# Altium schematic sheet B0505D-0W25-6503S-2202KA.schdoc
size 277 x 190 mm; Device: default297x210; Symbol: default297x210; Name: default297x210; Date: 2026.02.11; Rev: V1.2; Size: "A4"; Id: /; File: B0505D-0W25-6503S-2202KA; Sheet: /
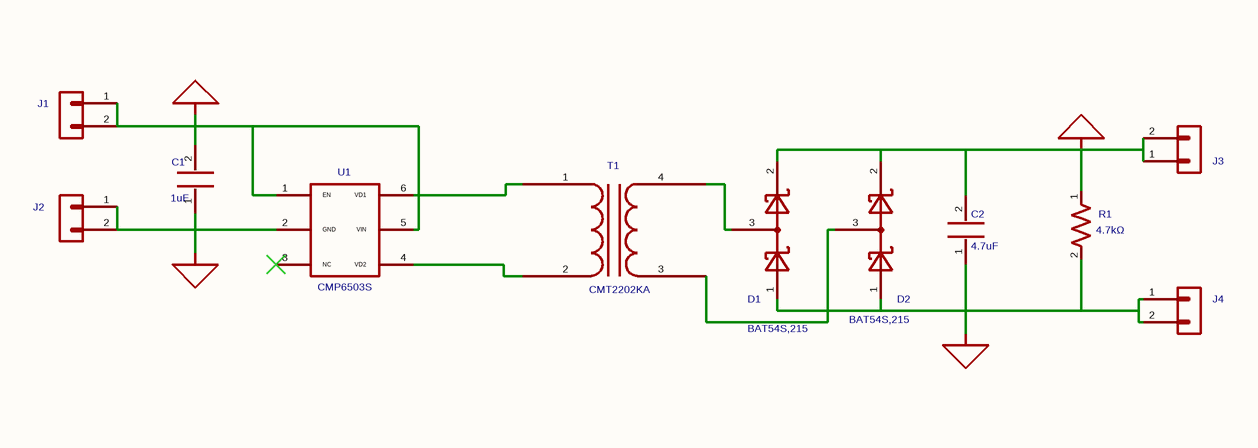
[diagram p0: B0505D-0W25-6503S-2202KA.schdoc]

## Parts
C1  1uF  [MYLibrary:C0603]
C2  4.7uF  [MYLibrary:C0603]
D1  BAT54S,215  [Package_TO_SOT_SMD:SOT-23]
D2  BAT54S,215  [Package_TO_SOT_SMD:SOT-23]
J1  KH-2.54PH180-1X2P-L11.5  [Connector_PinHeader_2.54mm:PinHeader_1x02_P2.54mm_Vertical]  (value not drawn)
J2  KH-2.54PH180-1X2P-L11.5  [Connector_PinHeader_2.54mm:PinHeader_1x02_P2.54mm_Vertical]  (value not drawn)
J3  KH-2.54PH180-1X2P-L11.5  [Connector_PinHeader_2.54mm:PinHeader_1x02_P2.54mm_Vertical]  (value not drawn)
J4  KH-2.54PH180-1X2P-L11.5  [Connector_PinHeader_2.54mm:PinHeader_1x02_P2.54mm_Vertical]  (value not drawn)
R1  4.7kΩ  [MYLibrary:R0603]
T1  CMT2202KA  [MYLibrary:CMT2202KA]
U1  CMP6503S  [MYLibrary:SOT-23-6]

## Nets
GND1: C1.1 J2.1(Pin_1) J2.2(Pin_2) U1.2(GND)
GND2: C2.1 D1.1 D2.1 J4.1(Pin_1) J4.2(Pin_2) R1.2
VCC1: C1.2 J1.1(Pin_1) J1.2(Pin_2) U1.1(EN) U1.5(VIN)
VCC2: C2.2 D1.2 D2.2 J3.1(Pin_1) J3.2(Pin_2) R1.1
NetD1_3: D1.3 T1.4(SB)
NetD2_3: D2.3 T1.3(SA)
NetT1_1: T1.1(AA) U1.6(VD1)
NetT1_2: T1.2(AB) U1.4(VD2)

Not connected (* = marked no-connect by the designer): U1 3(NC)*

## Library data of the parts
C1 = 0603B105K250NT: 容值:1uF;精度:±10%;额定电压:25V;温度系数:X7R;; Manufacturer: FH(风华); Symbol: My_Library_C; Add into BOM: yes; 3D Model: ac125912035d415993ca9572d50418b1; 3D Model Transform: 62.992,31.496,0,0,0,0,0,0,0; Tolerance: ±10%; Voltage Rating: 25V; Temperature Coefficient: X7R; ki_keywords: cap capacitor; ki_fp_filters: C_*; ModelName: C0603_L1.6-W0.8-H0.8
C2 = CL10A475KP8NNNC: 容值:4.7uF;精度:±10%;额定电压:10V;温度系数:X5R;; Manufacturer: SAMSUNG(三星); Symbol: My_Library_C; Add into BOM: yes; 3D Model: ac125912035d415993ca9572d50418b1; 3D Model Transform: 62.992,31.496,0,0,0,0,0,0,0; Tolerance: ±10%; Voltage Rating: 10V; Temperature Coefficient: X5R; ki_keywords: cap capacitor; ki_fp_filters: C_*; UniqueId: 21d50210554cb61f; ModelName: C0603_L1.6-W0.8-H0.8
D1 = BAT54S,215: 二极管配置:1对串联式;正向压降(Vf):800mV@100mA;直流反向耐压(Vr):30V;整流电流:200mA;; Manufacturer: Nexperia(安世); Symbol: Diode_BAT54S; Add into BOM: yes; 3D Model: 89cb27a44ab2466697082bb9fd73a7d0; 3D Model Transform: 114.173,110.236,0,90,0,0,0,0,0; Diode Configuration: 1对串联式; Voltage - DC Reverse(Vr): 30V; Current - Rectified: 200mA; Reverse Leakage Current (Ir): 2uA@25V; Non-Repetitive Peak Forward Surge Current: 600mA; ki_keywords: schottky diode; ki_fp_filters: SOT?23*; UniqueId: 07a0d5848cd81316; ModelName: SOT-23-3L_L2.9-W1.6-H1.1-LS2.8-P0.95
D2 = BAT54S,215: 二极管配置:1对串联式;正向压降(Vf):800mV@100mA;直流反向耐压(Vr):30V;整流电流:200mA;; Manufacturer: Nexperia(安世); Symbol: Diode_BAT54S; Add into BOM: yes; 3D Model: 89cb27a44ab2466697082bb9fd73a7d0; 3D Model Transform: 114.173,110.236,0,90,0,0,0,0,0; Diode Configuration: 1对串联式; Voltage - DC Reverse(Vr): 30V; Current - Rectified: 200mA; Reverse Leakage Current (Ir): 2uA@25V; Non-Repetitive Peak Forward Surge Current: 600mA; ki_keywords: schottky diode; ki_fp_filters: SOT?23*; ModelName: SOT-23-3L_L2.9-W1.6-H1.1-LS2.8-P0.95
J1 = KH-2.54PH180-1X2P-L11.5: 插针结构:1x2P;间距:2.54mm;行距:-;圆针/方针:方针;安装方式:直插;排数:单排;总PIN位数:2P;额定电流:3A;额定电压:-;配合针长度:6mm;塑高:2.5mm;端接针长度:3mm;触头材质:-;工作温度:-40℃~+105℃;颜色:黑色;; Manufacturer: kinghelm(金航标); Symbol: Connector_Generic_Conn_01x02; Add into BOM: yes; 3D Model: e35305ec3aa84b66b849f914b715e73f; 3D Model Transform: 200,100,0,0,0,0,0,0,-118.11; Pin Structure: 1x2P; Pitch: 2.54mm; Circluar Pins/Square Pins: 方针; Current Rating: 3A; ki_keywords: connector; ki_fp_filters: Connector*:*_1x??_*; UniqueId: 9f49826860c2c79d; ModelName: HDR2.54-M-LI-1X2P
J2 J4 = KH-2.54PH180-1X2P-L11.5: 插针结构:1x2P;间距:2.54mm;行距:-;圆针/方针:方针;安装方式:直插;排数:单排;总PIN位数:2P;额定电流:3A;额定电压:-;配合针长度:6mm;塑高:2.5mm;端接针长度:3mm;触头材质:-;工作温度:-40℃~+105℃;颜色:黑色;; Manufacturer: kinghelm(金航标); Symbol: Connector_Generic_Conn_01x02; Add into BOM: yes; 3D Model: e35305ec3aa84b66b849f914b715e73f; 3D Model Transform: 200,100,0,0,0,0,0,0,-118.11; Pin Structure: 1x2P; Pitch: 2.54mm; Circluar Pins/Square Pins: 方针; Current Rating: 3A; ki_keywords: connector; ki_fp_filters: Connector*:*_1x??_*; ModelName: HDR2.54-M-LI-1X2P
J3 = KH-2.54PH180-1X2P-L11.5: 插针结构:1x2P;间距:2.54mm;行距:-;圆针/方针:方针;安装方式:直插;排数:单排;总PIN位数:2P;额定电流:3A;额定电压:-;配合针长度:6mm;塑高:2.5mm;端接针长度:3mm;触头材质:-;工作温度:-40℃~+105℃;颜色:黑色;; Manufacturer: kinghelm(金航标); Symbol: Connector_Generic_Conn_01x02; Add into BOM: yes; 3D Model: e35305ec3aa84b66b849f914b715e73f; 3D Model Transform: 200,100,0,0,0,0,0,0,-118.11; Pin Structure: 1x2P; Pitch: 2.54mm; Circluar Pins/Square Pins: 方针; Current Rating: 3A; ki_keywords: connector; ki_fp_filters: Connector*:*_1x??_*; UniqueId: 6ca7fcf0d18ad80e; ModelName: HDR2.54-M-LI-1X2P
R1 = RC0603FR-074K7L: 电阻类型:厚膜电阻;阻值:4.7kΩ;精度:±1%;功率:100mW;工作电压:75V;温度系数:±100ppm/℃;; Manufacturer: YAGEO(国巨); Symbol: My_Library_R; Add into BOM: yes; 3D Model: fc143cca1e79419f9cd78b61e9279f08; 3D Model Transform: 31.8897,63.7794,0,90,0,0,0,0,0; Tolerance: ±1%; Power(Watts): 100mW; Voltage-Supply(Max): 75V; ki_keywords: R res resistor; ki_fp_filters: R_*; UniqueId: 4e166b190d4de1c3; ModelName: R0603
T1 = CMT2202KA: 电源变压器 SMD-8 隔离耐压：2.5KV 一次绕组：单路 二次绕组：单路 功率0.3W; Manufacturer: coileasy(线易); Symbol: Device_Transformer_1P_1S; Add into BOM: yes; 3D Model: 956a062a683d47c085e5f9b3660dc95d; 3D Model Transform: 354.33,216.9287,0,0,0,0,-0.001,-0.003,0; ki_keywords: transformer coil magnet; UniqueId: cf2c480e5945250c; ModelName: XFMR-SMD_CMT220KA
U1 = CMP6503S: CMP6503S 是低噪声、低 EMI 辐射的全桥式隔离电源变压器驱动器，特别适合于小型化的隔离电源方案，属于 线 易 ChipMate(CM) 系 列 的 电 源 解 决 方 案 。CMP6503S 内 部 集 成 两 对 N 型 和 P 型 功 率MOSFET，通过芯片内部集成振荡器提供具有精准时序和死区时间的互补驱动信号。驱动器芯片 CMP6503S和变压器配合必要的容阻和整流二极管，可以实现5.0V 输入/5.0V 输出的 200 mA 隔离非稳压电源；或者 3.3V 输入/3.3V 输出的 10; Manufacturer: coileasy(线易); Symbol: My_Library_VPS8504B; Add into BOM: yes; 3D Model: 7ba65df16e7b4570af156e925f9c37fe; 3D Model Transform: 114.173,114.173,0,90,0,0,0,0,0; Input Voltage: 3V~5.5V; Quiescent Current: 2.2mA; Origin Footprint: library:VPS8504B; UniqueId: 48a4a086d8c42a18; ModelName: SOT-23-5_L2.9-W1.6-P0.95-LS2.8-BR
